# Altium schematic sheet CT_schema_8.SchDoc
size 252 x 159 mm
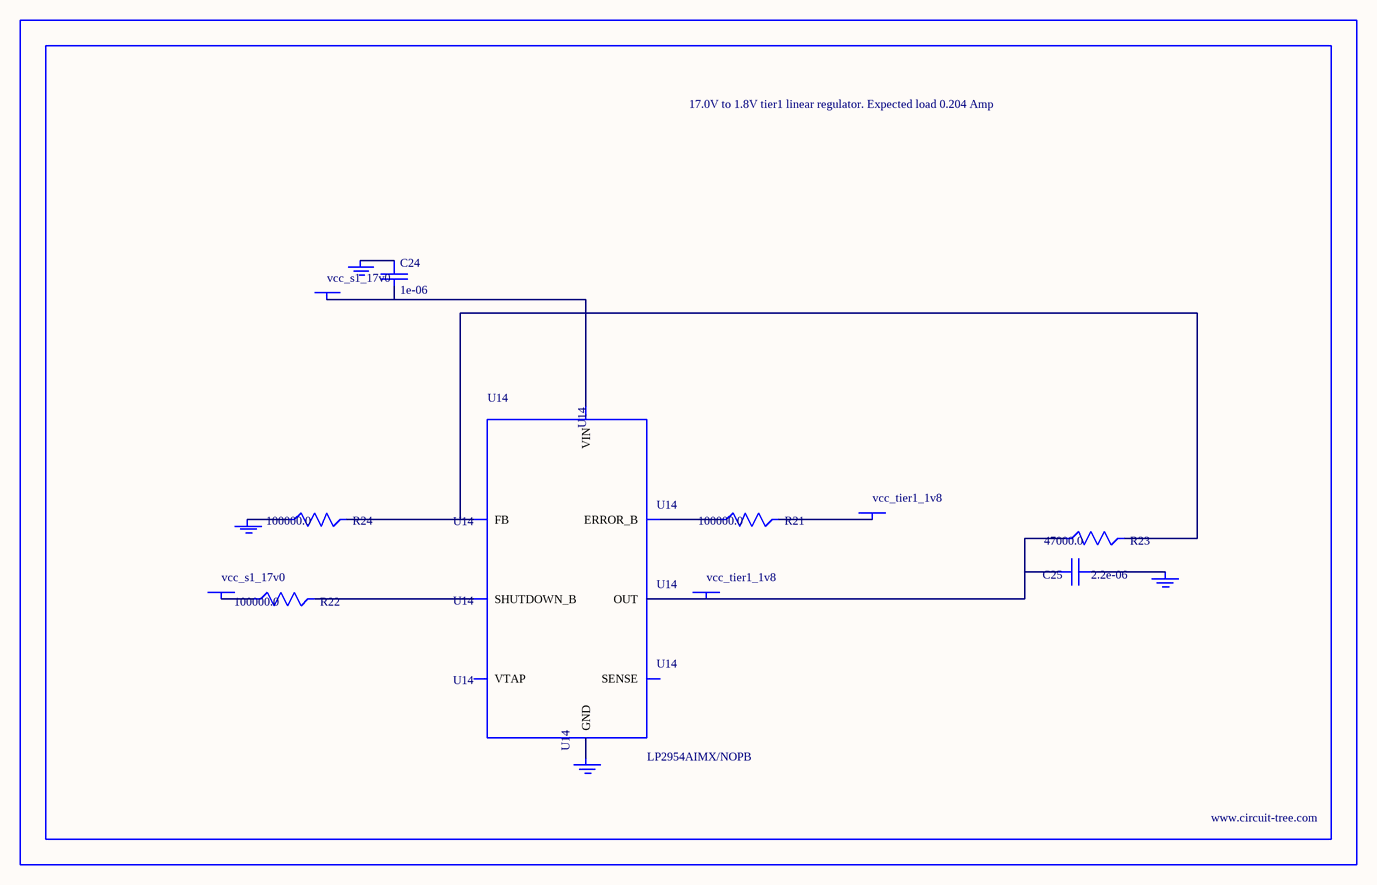
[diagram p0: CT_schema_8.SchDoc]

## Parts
BORDER7  (no value)
C24  1e-06  [EXV-9B]
C25  2.2e-06  [EXV-9B]
GND_INSTANCE_7_0  (no value)
GND_INSTANCE_7_1  (no value)
GND_INSTANCE_7_2  (no value)
GND_INSTANCE_7_3  (no value)
POWER_INSTANCE_7_0  vcc_s1_17v0
POWER_INSTANCE_7_1  vcc_tier1_1v8
POWER_INSTANCE_7_2  vcc_s1_17v0
POWER_INSTANCE_7_3  vcc_tier1_1v8
R21  100000.0  [R0603]
R22  100000.0  [R0603]
R23  47000.0  [R0603]
R24  100000.0  [R0603]
U14  LP2954AIMX/NOPB  [LP2954]

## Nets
NetC24_1: C24.1 GND_INSTANCE_7_2.0(GND)
NetC24_2: C24.2 POWER_INSTANCE_7_2.0(PWR) U14.8(VIN)
NetC25_1: C25.1 GND_INSTANCE_7_0.0(GND)
NetC25_2: C25.2 POWER_INSTANCE_7_3.0(PWR) R23.1 U14.1(OUT)
NetGND_INSTANCE_7_1_0: GND_INSTANCE_7_1.0(GND) R24.1
NetGND_INSTANCE_7_3_0: GND_INSTANCE_7_3.0(GND) U14.4(GND)
NetPOWER_INSTANCE_7_0_0: POWER_INSTANCE_7_0.0(PWR) R22.1
NetPOWER_INSTANCE_7_1_0: POWER_INSTANCE_7_1.0(PWR) R21.2
NetR21_1: R21.1 U14.5(ERROR_B)
NetR22_2: R22.2 U14.3(SHUTDOWN_B)
NetR23_2: R23.2 R24.2 U14.7(FB)

Not connected (* = marked no-connect by the designer): U14 2(SENSE) 6(VTAP)

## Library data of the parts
BORDER7 = BORDER_PAGE7
C24 = EDK105M050A9BAA
C25 = EDK225M050A9BAA
GND_INSTANCE_7_0-GND_INSTANCE_7_3 = GND
POWER_INSTANCE_7_0-POWER_INSTANCE_7_3 = PWR
R21 R22 R24 = RC0603JR-07100KL
R23 = RC0603JR-0747KL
